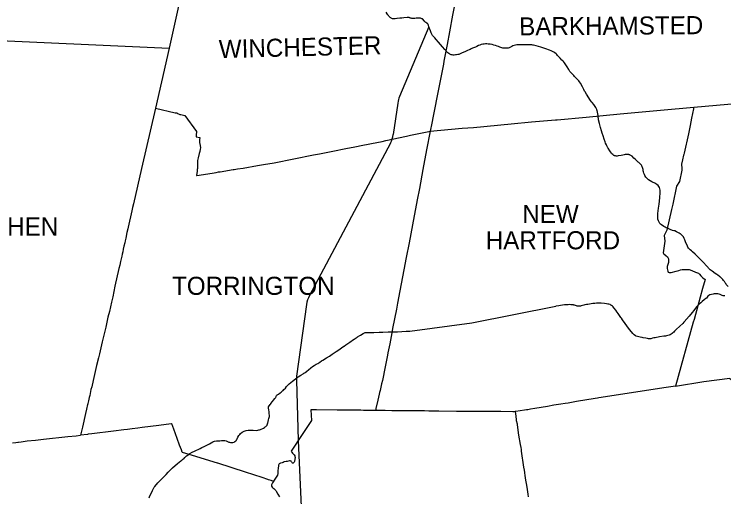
# Model space of a CAD drawing. Extents: x 0 to 2603, y -226 to 830.
# Drawn here: x 107.7 to 160.6, y 640.7 to 676.8 of the extents above; entities that cross this region are included whole.
import ezdxf

# ---------------------------------------------------------------- set-up
doc = ezdxf.new("R2010")
doc.units = 0
for name, color, linetype in [('CT_TSH_Map_Town_Limits', 7, 'Continuous'), ('CT_TSH_Map_Town_Text', 7, 'Continuous'), ('CT_TSH_Map_US_and_State_Routes', 7, 'Continuous')]:
    doc.layers.add(name, color=color, linetype=linetype)

msp = doc.modelspace()

# ---------------------------------------------------------------- linework, layer by layer
at = {"layer": 'CT_TSH_Map_Town_Limits'}
for points in [[(142.198, 686.552), (142.15, 686.309), (141.745, 684.019), (141.62, 683.255), (141.187, 680.773), (141.113, 680.321), (140.913, 679.551), (140.896, 679.495), (140.856, 679.291), (140.811, 679.034), (140.725, 678.584), (140.613, 677.959), (140.441, 677.067), (140.378, 676.703), (140.137, 675.45), (139.965, 674.513), (139.87, 673.997), (139.728, 673.254), (139.696, 673.043), (139.23, 670.666), (139.03, 669.643), (138.929, 669.148), (138.837, 668.643), (138.715, 668.03)], [(121.633, 685.104), (119.215, 674.224)], [(158.379, 669.838), (162.606, 670.208), (162.883, 670.24), (164.49, 676.032)], [(102.09, 675.051), (103.633, 674.96), (104.397, 674.915), (119.215, 674.224)], [(119.215, 674.224), (118.649, 671.731), (118.2, 669.749)], [(118.2, 669.749), (117.164, 665.263), (116.552, 662.607), (116.484, 662.337), (116.435, 662.092), (116.155, 660.872), (116.132, 660.754), (116.067, 660.483), (115.974, 660.058), (115.924, 659.853), (115.898, 659.704), (115.842, 659.46), (115.792, 659.222), (115.75, 659.042), (115.711, 658.853), (115.675, 658.719), (115.656, 658.612), (115.581, 658.301), (115.529, 658.04), (115.469, 657.797), (115.172, 656.465), (115.002, 655.668), (114.915, 655.285), (114.757, 654.582), (114.652, 654.145), (114.486, 653.4), (114.225, 652.315), (114.008, 651.411), (113.945, 651.123), (113.803, 650.538), (113.545, 649.439), (113.44, 648.961), (113.383, 648.747), (113.288, 648.307), (113.244, 648.148), (113.191, 647.91), (113.142, 647.716), (113.137, 647.673), (113.128, 647.645), (113.055, 647.299), (112.975, 646.965), (112.748, 645.947), (112.6, 645.343)], [(118.2, 669.749), (119.677, 669.399), (119.779, 669.406), (119.811, 669.396), (119.852, 669.362), (119.914, 669.326), (120.027, 669.29), (120.093, 669.275), (120.385, 669.209), (121.257, 668.008), (121.24, 667.739), (121.239, 667.613), (121.512, 667.574), (121.499, 667.534), (121.485, 667.407), (121.479, 667.265), (121.489, 667.18), (121.537, 666.977), (121.553, 666.796), (121.538, 666.691), (121.5, 666.52), (121.458, 666.372), (121.381, 666.039), (121.333, 665.856), (121.327, 665.818), (121.325, 665.545), (121.326, 665.239), (121.322, 665.183), (121.303, 665.048), (121.276, 664.882), (121.251, 664.751), (121.251, 664.718), (121.296, 664.719), (122.432, 664.911), (122.724, 664.957), (122.914, 664.998), (123.018, 665.011), (123.991, 665.165), (124.062, 665.181), (124.326, 665.223), (124.732, 665.272), (125.821, 665.465), (126.26, 665.545), (127.055, 665.68), (129.985, 666.26), (130.438, 666.343), (131.303, 666.52), (132.523, 666.761), (132.683, 666.791), (133.077, 666.873), (133.327, 666.917), (133.425, 666.938), (134.32, 667.119), (135.112, 667.266), (135.389, 667.336), (136.942, 667.672), (137.236, 667.739), (138.346, 667.956), (138.594, 668.002), (138.715, 668.03)], [(138.715, 668.03), (141.105, 668.267), (141.946, 668.323), (144.741, 668.577), (146.266, 668.722), (148.059, 668.879), (148.182, 668.885), (150.341, 669.081), (152.882, 669.326), (155.889, 669.604), (158.379, 669.838)], [(158.379, 669.838), (158.356, 669.731), (158.35, 669.716), (158.225, 668.997), (158.115, 668.455), (157.987, 667.849), (157.658, 666.398), (157.631, 666.293), (157.625, 666.242), (157.551, 665.895), (157.46, 665.575), (157.501, 665.245), (157.501, 665.202), (157.49, 665.117), (157.322, 664.293), (157.102, 663.932), (156.822, 662.594), (156.729, 662.193), (156.374, 660.637), (156.177, 660.244), (156.229, 659.818), (156.086, 658.969), (156.115, 658.909), (156.157, 658.871), (156.294, 658.77), (156.413, 658.662), (156.503, 658.508), (156.499, 658.338), (156.488, 658.225), (156.448, 658.087), (156.414, 658.002), (156.397, 657.938), (156.405, 657.789), (156.434, 657.577), (156.478, 657.522), (156.546, 657.5), (156.606, 657.489), (156.691, 657.481), (157.073, 657.591), (157.271, 657.632), (157.382, 657.683), (157.511, 657.718), (157.621, 657.702), (157.71, 657.701), (157.95, 657.711), (158.028, 657.704), (158.234, 657.638), (158.349, 657.58), (158.414, 657.569), (158.521, 657.515), (158.729, 657.429), (158.801, 657.367), (158.918, 657.242), (159.015, 657.13), (159.07, 657.082), (159.233, 656.974), (159.044, 656.284), (158.868, 655.66), (158.406, 653.991), (158.341, 653.771), (157.01, 649.012)], [(138.715, 668.03), (138.442, 666.636), (138.157, 665.173), (137.897, 663.749), (137.734, 662.921), (137.379, 661.04), (137.125, 659.715), (136.915, 658.619), (136.743, 657.691), (136.443, 656.131), (136.274, 655.205), (136.179, 654.759), (135.897, 653.303), (135.842, 652.982), (135.686, 652.172), (135.546, 651.492), (135.514, 651.323), (135.337, 650.456), (135.145, 649.434), (135.07, 649.187), (134.984, 648.808), (134.96, 648.687), (134.922, 648.544), (134.892, 648.4), (134.789, 647.968), (134.645, 647.327), (134.639, 647.294), (134.617, 647.192)], [(157.01, 649.012), (159.123, 649.343), (161.084, 649.599), (161.103, 649.564), (161.183, 649.498), (161.265, 649.448), (161.464, 649.358), (161.647, 649.3), (161.679, 649.27), (161.707, 649.232), (161.785, 649.202), (161.84, 649.175), (161.903, 649.128), (161.948, 649.066), (161.955, 649.043), (162.08, 649.071)], [(157.01, 649.012), (156.316, 648.905), (151.307, 648.125), (151.199, 648.11), (151.032, 648.081), (149.636, 647.86), (149.013, 647.749), (148.789, 647.715), (148.45, 647.671), (148.122, 647.607), (147.927, 647.576), (147.454, 647.493), (146.521, 647.337), (146.192, 647.286), (146.003, 647.252), (145.899, 647.238), (145.747, 647.208), (145.093, 647.104), (145.056, 647.103)], [(134.617, 647.192), (134.487, 647.186), (134.418, 647.19), (133.922, 647.196), (133.865, 647.197), (133.731, 647.199), (133.538, 647.206), (132.768, 647.208), (131.76, 647.217), (130.22, 647.239), (129.79, 647.247), (129.788, 647.242), (129.844, 646.433), (129.349, 645.698), (128.996, 645.168), (128.466, 644.37), (128.32, 644.148), (128.352, 644.11), (128.383, 644.088), (128.433, 644.01), (128.485, 643.968), (128.546, 643.886), (128.59, 643.798), (128.612, 643.748), (128.622, 643.683), (128.604, 643.549), (128.572, 643.39), (128.539, 643.323), (128.506, 643.277), (128.475, 643.263), (128.439, 643.267), (128.397, 643.293), (128.371, 643.324), (128.344, 643.36), (128.317, 643.402), (128.293, 643.415), (128.263, 643.422), (128.193, 643.422), (128.026, 643.393), (127.963, 643.388), (127.794, 643.349), (127.723, 643.321), (127.655, 643.289), (127.542, 643.257), (127.489, 643.234), (127.441, 643.203), (127.415, 643.166), (127.392, 643.109), (127.346, 642.825), (127.335, 642.729), (127.335, 642.488), (127.313, 642.371), (127.269, 642.283), (127.017, 641.921), (127.001, 641.895)], [(145.056, 647.103), (145.029, 647.091), (144.875, 647.095), (143.983, 647.109), (143.9, 647.118), (143.772, 647.115), (143.404, 647.112), (142.695, 647.12), (142.233, 647.119), (141.861, 647.114), (141.771, 647.122), (141.467, 647.127), (140.67, 647.127), (139.362, 647.14), (138.849, 647.15), (138.614, 647.149), (138.275, 647.156), (137.236, 647.166), (135.849, 647.176), (135.355, 647.184), (134.663, 647.189), (134.617, 647.192)], [(145.056, 647.103), (145.067, 646.963), (145.119, 646.527), (145.131, 646.449), (145.188, 646.202), (145.209, 646.109), (145.302, 645.357), (145.425, 644.657), (145.466, 644.433), (145.485, 644.281), (145.508, 644.148), (145.671, 642.958), (145.713, 642.726), (145.743, 642.568), (145.753, 642.536), (145.771, 642.34), (145.806, 642.159), (145.806, 642.132), (145.908, 641.466), (145.943, 641.292), (146.002, 640.945), (146.03, 640.736)], [(127.001, 641.895), (126.834, 641.954), (126.641, 642.015), (126.595, 642.035), (126.157, 642.184), (124.919, 642.584), (122.852, 643.259), (122.831, 643.263), (120.953, 643.843), (120.216, 644.064), (120.19, 644.081), (120.129, 644.248), (119.997, 644.605), (119.823, 645.095), (119.571, 645.786), (119.426, 646.203), (119.404, 646.196), (118.987, 646.141), (118.448, 646.081), (117.828, 645.998), (117.203, 645.921), (116.879, 645.88), (116.469, 645.834), (116.103, 645.784), (115.827, 645.753), (115.072, 645.651), (113.449, 645.453), (113.164, 645.419), (113.128, 645.41), (112.6, 645.343)], [(107.53, 644.765), (107.764, 644.793), (107.914, 644.817), (107.978, 644.832), (108.159, 644.854), (108.627, 644.928), (109.235, 644.981), (109.832, 645.051), (111.645, 645.242), (112.265, 645.303), (112.6, 645.343)], [(127.001, 641.895), (126.923, 641.781), (126.875, 641.698), (126.855, 641.631), (126.868, 641.535), (126.899, 641.476), (126.962, 641.421), (127.024, 641.375), (127.125, 641.278), (127.173, 641.225), (127.212, 641.171), (127.331, 640.938), (127.455, 640.745)]]:
    msp.add_lwpolyline(points, dxfattribs=at)
at = {"layer": 'CT_TSH_Map_US_and_State_Routes'}
for p, q in [((136.978, 676.521), (136.726, 676.497)), ((138.02, 676.454), (137.987, 676.462)), ((138.613, 675.826), (136.422, 670.631)), ((138.613, 675.826), (138.57, 675.933)), ((138.726, 675.535), (138.613, 675.826)), ((138.789, 675.371), (138.726, 675.535)), ((138.996, 675.059), (138.884, 675.188)), ((145.747, 674.481), (145.443, 674.489)), ((140.087, 673.833), (140.025, 673.88)), ((147.186, 674.227), (146.962, 674.299)), ((147.333, 674.178), (147.186, 674.227)), ((148.4, 673.482), (148.204, 673.695)), ((148.535, 673.348), (148.4, 673.482)), ((148.729, 673.131), (148.66, 673.228)), ((149.794, 671.794), (149.481, 672.125)), ((150.384, 670.79), (150.264, 670.974)), ((136.285, 670.139), (135.946, 667.791)), ((135.733, 667.138), (129.69, 655.768)), ((152.115, 666.563), (151.992, 666.761)), ((155.24, 664.255), (154.995, 664.416)), ((156.141, 660.934), (155.965, 661.05)), ((157.999, 659.308), (157.95, 659.388)), ((158.536, 658.799), (158.477, 658.857)), ((158.75, 658.592), (158.536, 658.799)), ((160.173, 657.28), (160.097, 657.335)), ((129.475, 655.103), (128.737, 649.759)), ((133.25, 652.66), (133.281, 652.681)), ((133.281, 652.681), (133.456, 652.789)), ((133.456, 652.789), (133.505, 652.818)), ((133.95, 653.009), (134.044, 653.009)), ((134.361, 653.018), (134.494, 653.021)), ((135.965, 653.061), (136.264, 653.073)), ((132.415, 652.096), (132.706, 652.298)), ((132.706, 652.298), (132.973, 652.484)), ((131.817, 651.679), (132.253, 651.983)), ((130.698, 650.944), (130.968, 651.111)), ((130.968, 651.111), (131.187, 651.252)), ((131.187, 651.252), (131.395, 651.391)), ((129.926, 650.467), (130.056, 650.548)), ((130.056, 650.548), (130.201, 650.638)), ((130.201, 650.638), (130.317, 650.71)), ((130.317, 650.71), (130.464, 650.8)), ((130.464, 650.8), (130.602, 650.885)), ((130.602, 650.885), (130.698, 650.944)), ((129.491, 650.126), (129.63, 650.237)), ((129.63, 650.237), (129.804, 650.38)), ((129.804, 650.38), (129.926, 650.467)), ((128.714, 649.593), (128.747, 649.62)), ((128.747, 649.62), (128.79, 649.651)), ((128.79, 649.651), (128.827, 649.68)), ((128.827, 649.68), (128.859, 649.701)), ((128.859, 649.701), (129.049, 649.823)), ((129.049, 649.823), (129.225, 649.931)), ((129.225, 649.931), (129.279, 649.966)), ((128.719, 649.425), (128.853, 644.968)), ((127.581, 648.568), (127.682, 648.653)), ((127.682, 648.653), (127.723, 648.691)), ((127.723, 648.691), (127.791, 648.756)), ((127.791, 648.756), (127.892, 648.865)), ((126.926, 647.852), (127.019, 647.968)), ((127.019, 647.968), (127.111, 648.084)), ((127.205, 648.226), (127.216, 648.271)), ((127.216, 648.271), (127.233, 648.297)), ((127.233, 648.297), (127.24, 648.307)), ((126.623, 647.471), (126.748, 647.628)), ((126.639, 647.37), (126.623, 647.471)), ((126.748, 647.628), (126.801, 647.692)), ((126.577, 646.249), (126.638, 646.481)), ((125.956, 645.751), (126.041, 645.778)), ((122.078, 644.636), (122.221, 644.709)), ((122.951, 644.933), (122.992, 644.937)), ((128.854, 644.938), (129.353, 633.855)), ((121.523, 644.361), (121.646, 644.421)), ((121.646, 644.421), (121.838, 644.514)), ((121.838, 644.514), (122.078, 644.636)), ((118.385, 641.782), (118.599, 642.008)), ((117.717, 640.676), (117.788, 640.822))]:
    msp.add_line(p, q, dxfattribs=at)
for points in [[(135.977, 676.419), (135.934, 676.42), (135.89, 676.427), (135.845, 676.439), (135.797, 676.46), (135.755, 676.487), (135.717, 676.517), (135.658, 676.57), (135.615, 676.617), (135.582, 676.667), (135.555, 676.714), (135.492, 676.804), (135.42, 676.906)], [(136.726, 676.497), (136.584, 676.481), (136.433, 676.465), (136.241, 676.446)], [(137.103, 676.526), (137.078, 676.532), (137.025, 676.531), (136.978, 676.521)], [(137.196, 676.49), (137.168, 676.507), (137.137, 676.52), (137.103, 676.526)], [(137.295, 676.46), (137.244, 676.472), (137.196, 676.49)], [(136.241, 676.446), (136.206, 676.443), (136.082, 676.429), (135.977, 676.419)], [(137.461, 676.442), (137.395, 676.444), (137.344, 676.451), (137.295, 676.46)], [(137.65, 676.467), (137.566, 676.45), (137.512, 676.445), (137.461, 676.442)], [(137.987, 676.462), (137.941, 676.47), (137.892, 676.477), (137.816, 676.481), (137.751, 676.479), (137.693, 676.474), (137.65, 676.467)], [(138.123, 676.422), (138.093, 676.433), (138.02, 676.454)], [(138.463, 676.103), (138.414, 676.136), (138.382, 676.154), (138.346, 676.181), (138.318, 676.206), (138.272, 676.254), (138.123, 676.422)], [(138.524, 676.037), (138.508, 676.06), (138.496, 676.073), (138.479, 676.089), (138.463, 676.103)], [(138.57, 675.933), (138.544, 676.001), (138.524, 676.037)], [(138.884, 675.188), (138.834, 675.268), (138.8, 675.336), (138.789, 675.371)], [(139.32, 674.685), (139.153, 674.878), (139.055, 674.993), (138.996, 675.059)], [(140.025, 673.88), (139.945, 673.958), (139.894, 674.02), (139.865, 674.059), (139.811, 674.124), (139.634, 674.326), (139.472, 674.511), (139.32, 674.685)], [(142.32, 674.423), (142.18, 674.361), (142.076, 674.316), (141.867, 674.22)], [(143.904, 674.312), (143.815, 674.357), (143.711, 674.393), (143.587, 674.434), (143.469, 674.466), (143.321, 674.495), (143.177, 674.522), (143.033, 674.541), (142.937, 674.545), (142.842, 674.543), (142.735, 674.535), (142.625, 674.518), (142.518, 674.493), (142.415, 674.461), (142.32, 674.423)], [(145.443, 674.489), (145.337, 674.49), (145.251, 674.487), (145.166, 674.478), (145.074, 674.462), (144.977, 674.434), (144.883, 674.398), (144.808, 674.36)], [(146.51, 674.441), (146.416, 674.458), (146.372, 674.463), (146.281, 674.468), (145.747, 674.481)], [(146.962, 674.299), (146.621, 674.41), (146.51, 674.441)], [(141.055, 673.854), (140.933, 673.8), (140.845, 673.77), (140.773, 673.751), (140.679, 673.732), (140.603, 673.723), (140.507, 673.718), (140.42, 673.721), (140.346, 673.727), (140.278, 673.739), (140.215, 673.763)], [(141.867, 674.22), (141.767, 674.174), (141.701, 674.144), (141.611, 674.106), (141.485, 674.047), (141.33, 673.978), (141.055, 673.854)], [(144.531, 674.243), (144.45, 674.227), (144.389, 674.222), (144.317, 674.22), (144.231, 674.221), (144.128, 674.237), (144.051, 674.257), (143.972, 674.284), (143.904, 674.312)], [(144.808, 674.36), (144.711, 674.304), (144.657, 674.28), (144.595, 674.26), (144.531, 674.243)], [(148.204, 673.695), (148.152, 673.753), (148.101, 673.801), (148.017, 673.873), (147.93, 673.935), (147.842, 673.989), (147.729, 674.045), (147.614, 674.087), (147.333, 674.178)], [(140.215, 673.763), (140.172, 673.784), (140.138, 673.803), (140.087, 673.833)], [(148.66, 673.228), (148.605, 673.279), (148.535, 673.348)], [(149.481, 672.125), (149.425, 672.189), (149.26, 672.369), (149.138, 672.495), (149.073, 672.597), (149.048, 672.641), (148.932, 672.828), (148.729, 673.131)], [(150.069, 671.336), (149.919, 671.618), (149.859, 671.71), (149.794, 671.794)], [(150.264, 670.974), (150.232, 671.02), (150.163, 671.15), (150.069, 671.336)], [(151.14, 669.665), (151.096, 669.749), (151.061, 669.811), (151.02, 669.876), (150.965, 669.949), (150.91, 670.02), (150.789, 670.168), (150.753, 670.22), (150.679, 670.338), (150.384, 670.79)], [(151.253, 669.06), (151.248, 669.218), (151.223, 669.327), (151.193, 669.457), (151.167, 669.58), (151.156, 669.615), (151.14, 669.665)], [(151.992, 666.761), (151.978, 666.793), (151.902, 666.943), (151.867, 667.007), (151.803, 667.138), (151.769, 667.23), (151.694, 667.44), (151.617, 667.682), (151.548, 667.897), (151.503, 668.058), (151.43, 668.321), (151.35, 668.612), (151.276, 668.875), (151.264, 668.972), (151.253, 669.06)], [(152.391, 666.237), (152.359, 666.258), (152.329, 666.285), (152.273, 666.343), (152.231, 666.393), (152.165, 666.488), (152.115, 666.563)], [(152.527, 666.184), (152.496, 666.192), (152.465, 666.204), (152.447, 666.212), (152.42, 666.222), (152.391, 666.237)], [(153.559, 666.279), (153.528, 666.288), (153.498, 666.293), (153.464, 666.299), (153.412, 666.304), (153.356, 666.303), (153.305, 666.3), (153.249, 666.291), (153.193, 666.28), (153.081, 666.258), (152.955, 666.232), (152.739, 666.185), (152.676, 666.177), (152.583, 666.177), (152.527, 666.184)], [(154.233, 665.733), (154.015, 665.937), (153.92, 666.031), (153.784, 666.164), (153.741, 666.196), (153.693, 666.225), (153.645, 666.248), (153.598, 666.267), (153.559, 666.279)], [(154.469, 665.49), (154.425, 665.548), (154.385, 665.594), (154.341, 665.638), (154.295, 665.677), (154.28, 665.691), (154.233, 665.733)], [(154.63, 664.994), (154.617, 665.076), (154.605, 665.173), (154.583, 665.262), (154.563, 665.318), (154.533, 665.382), (154.498, 665.445), (154.469, 665.49)], [(154.995, 664.416), (154.881, 664.517), (154.805, 664.608), (154.736, 664.724), (154.698, 664.798), (154.653, 664.907), (154.63, 664.994)], [(155.716, 663.98), (155.627, 664.063), (155.551, 664.112), (155.464, 664.15), (155.301, 664.226), (155.24, 664.255)], [(155.708, 661.887), (155.746, 662.301), (155.794, 662.596), (155.85, 663.054), (155.886, 663.451), (155.88, 663.625), (155.859, 663.732), (155.824, 663.828), (155.772, 663.915), (155.716, 663.98)], [(155.965, 661.05), (155.911, 661.097), (155.859, 661.154), (155.789, 661.255), (155.743, 661.35), (155.712, 661.459), (155.694, 661.58), (155.698, 661.713), (155.708, 661.887)], [(156.624, 660.695), (156.517, 660.737), (156.448, 660.77), (156.392, 660.799), (156.319, 660.832), (156.256, 660.868), (156.141, 660.934)], [(156.904, 660.602), (156.799, 660.63), (156.624, 660.695)], [(157.776, 659.785), (157.712, 659.939), (157.675, 660.032), (157.605, 660.152), (157.551, 660.219), (157.503, 660.27), (157.452, 660.316), (157.419, 660.345), (157.376, 660.376), (157.29, 660.43), (157.085, 660.527), (156.959, 660.587), (156.904, 660.602)], [(157.95, 659.388), (157.912, 659.457), (157.776, 659.785)], [(158.477, 658.857), (158.29, 659.035), (158.212, 659.105), (158.104, 659.188), (158.071, 659.222), (157.999, 659.308)], [(159.379, 657.944), (159.06, 658.283), (158.75, 658.592)], [(160.097, 657.335), (159.98, 657.417), (159.752, 657.581), (159.608, 657.697), (159.487, 657.819), (159.458, 657.856), (159.379, 657.944)], [(160.947, 656.433), (160.871, 656.516), (160.812, 656.586), (160.768, 656.656), (160.718, 656.73), (160.666, 656.82), (160.612, 656.894), (160.554, 656.958), (160.52, 656.994), (160.501, 657.011), (160.479, 657.032), (160.448, 657.065), (160.391, 657.125), (160.358, 657.156), (160.336, 657.171), (160.311, 657.185), (160.268, 657.212), (160.173, 657.28)], [(160.692, 655.747), (160.586, 655.76), (160.512, 655.777), (160.448, 655.799), (160.355, 655.839), (160.29, 655.863), (160.188, 655.889), (160.084, 655.899), (160.012, 655.899), (159.91, 655.891), (159.819, 655.875), (159.695, 655.851), (159.585, 655.811), (159.511, 655.771), (159.441, 655.719), (159.376, 655.647), (159.324, 655.579), (159.278, 655.537), (159.168, 655.441), (159.015, 655.318)], [(159.015, 655.318), (158.912, 655.229), (158.797, 655.122), (158.621, 654.942), (158.522, 654.833), (158.376, 654.653), (158.252, 654.494), (158.043, 654.234), (157.677, 653.807), (157.642, 653.773), (157.556, 653.695)], [(136.264, 653.073), (136.911, 653.102), (137.115, 653.111), (137.183, 653.114), (141.815, 653.742), (148.08, 654.973)], [(148.31, 655.012), (148.113, 654.979), (148.08, 654.973)], [(148.421, 655.029), (148.31, 655.012)], [(148.593, 655.052), (148.421, 655.029)], [(149.42, 655.061), (149.407, 655.066), (149.362, 655.074), (149.307, 655.081), (149.217, 655.088), (149.097, 655.089), (149.011, 655.087), (148.919, 655.084), (148.811, 655.076), (148.721, 655.067), (148.593, 655.052)], [(149.487, 655.044), (149.42, 655.061)], [(150.249, 655.068), (150.182, 655.054), (150.072, 655.027), (149.974, 654.996), (149.933, 654.986), (149.88, 654.977), (149.828, 654.971), (149.771, 654.971), (149.71, 654.976), (149.673, 654.984), (149.628, 654.995), (149.553, 655.021), (149.487, 655.044)], [(152.601, 654.627), (152.581, 654.653), (152.421, 654.858), (152.36, 654.927), (152.311, 654.974), (152.253, 655.018), (152.201, 655.051), (152.131, 655.089), (152.053, 655.118), (152.014, 655.129), (151.96, 655.131), (151.858, 655.142), (151.717, 655.166), (151.477, 655.188), (151.262, 655.195), (151.127, 655.192), (151, 655.185), (150.854, 655.17), (150.723, 655.152), (150.592, 655.127), (150.471, 655.102), (150.377, 655.09), (150.249, 655.068)], [(152.945, 654.126), (152.833, 654.287), (152.73, 654.435), (152.601, 654.627)], [(152.978, 654.076), (152.945, 654.126)], [(153.265, 653.682), (153.067, 653.953), (152.978, 654.076)], [(154.273, 652.678), (154.175, 652.701), (154.092, 652.734), (154.026, 652.766), (153.935, 652.832), (153.879, 652.882), (153.83, 652.935), (153.735, 653.051), (153.588, 653.24), (153.396, 653.502), (153.265, 653.682)], [(157.077, 653.236), (157.025, 653.182), (156.949, 653.099), (156.884, 653.031), (156.819, 652.975), (156.76, 652.93), (156.688, 652.891)], [(157.344, 653.494), (157.077, 653.236)], [(157.556, 653.695), (157.344, 653.494)], [(132.973, 652.484), (133.032, 652.525), (133.25, 652.66)], [(133.505, 652.818), (133.702, 652.942), (133.757, 652.97), (133.809, 652.99), (133.849, 653)], [(133.849, 653), (133.88, 653.005), (133.913, 653.01), (133.95, 653.009)], [(134.044, 653.009), (134.215, 653.014), (134.361, 653.018)], [(134.494, 653.021), (134.898, 653.034), (135.181, 653.041), (135.577, 653.052), (135.937, 653.061), (135.965, 653.061)], [(154.519, 652.636), (154.381, 652.662), (154.273, 652.678)], [(156.688, 652.891), (156.621, 652.847), (156.538, 652.81), (156.442, 652.781), (156.356, 652.761), (156.266, 652.75), (156.143, 652.737), (155.822, 652.681), (155.509, 652.62)], [(154.617, 652.614), (154.519, 652.636)], [(155.166, 652.547), (155.093, 652.543), (155.001, 652.545), (154.935, 652.554), (154.794, 652.582), (154.617, 652.614)], [(155.509, 652.62), (155.4, 652.603), (155.313, 652.579), (155.166, 652.547)], [(131.395, 651.391), (131.683, 651.584), (131.817, 651.679)], [(132.253, 651.983), (132.273, 651.997), (132.415, 652.096)], [(129.279, 649.966), (129.346, 650.009), (129.372, 650.027), (129.382, 650.035), (129.461, 650.099), (129.491, 650.126)], [(128.526, 649.449), (128.553, 649.471), (128.647, 649.546), (128.664, 649.557)], [(128.664, 649.557), (128.683, 649.568), (128.714, 649.593)], [(127.892, 648.865), (127.988, 648.978), (128.039, 649.037), (128.113, 649.117), (128.183, 649.176)], [(128.183, 649.176), (128.436, 649.374), (128.526, 649.449)], [(127.303, 648.37), (127.339, 648.394), (127.376, 648.418)], [(127.376, 648.418), (127.494, 648.503), (127.581, 648.568)], [(127.111, 648.084), (127.147, 648.127), (127.182, 648.173), (127.197, 648.201), (127.205, 648.226)], [(127.24, 648.307), (127.259, 648.331), (127.283, 648.354), (127.303, 648.37)], [(126.688, 646.998), (126.676, 647.086), (126.653, 647.241), (126.639, 647.37)], [(126.801, 647.692), (126.817, 647.712), (126.926, 647.852)], [(126.703, 646.731), (126.71, 646.774), (126.708, 646.848), (126.695, 646.942), (126.688, 646.998)], [(126.638, 646.481), (126.664, 646.582), (126.703, 646.731)], [(126.041, 645.778), (126.25, 645.879), (126.338, 645.926), (126.397, 645.966), (126.431, 645.989), (126.48, 646.04)], [(126.48, 646.04), (126.506, 646.071), (126.527, 646.107), (126.529, 646.112), (126.545, 646.143)], [(126.545, 646.143), (126.558, 646.175), (126.569, 646.209), (126.577, 646.249)], [(124.292, 645.083), (124.349, 645.21), (124.425, 645.325), (124.484, 645.397), (124.549, 645.463), (124.677, 645.567), (124.82, 645.642), (124.975, 645.696), (125.129, 645.724), (125.252, 645.721), (125.5, 645.718), (125.708, 645.709), (125.831, 645.721), (125.924, 645.737), (125.956, 645.751)], [(122.221, 644.709), (122.477, 644.846), (122.535, 644.874)], [(122.535, 644.874), (122.611, 644.899), (122.743, 644.916), (122.896, 644.931), (122.951, 644.933)], [(122.992, 644.937), (123.127, 644.948), (123.234, 644.95), (123.37, 644.942)], [(123.37, 644.942), (123.472, 644.924), (123.53, 644.904)], [(123.53, 644.904), (123.676, 644.838), (123.712, 644.824)], [(123.712, 644.824), (123.791, 644.801), (123.875, 644.792), (123.969, 644.796), (124.071, 644.817), (124.129, 644.865), (124.184, 644.921), (124.238, 644.984), (124.277, 645.043), (124.292, 645.083)], [(120.521, 643.799), (120.649, 643.891), (120.772, 643.972), (120.942, 644.072), (121.113, 644.163), (121.523, 644.361)], [(120.082, 643.429), (120.16, 643.484), (120.247, 643.547), (120.302, 643.59), (120.394, 643.671), (120.521, 643.799)], [(119.143, 642.588), (119.316, 642.764), (119.462, 642.906), (119.831, 643.235), (120.082, 643.429)], [(118.599, 642.008), (118.805, 642.226), (118.899, 642.325), (118.988, 642.42), (119.143, 642.588)], [(117.788, 640.822), (117.889, 641.033), (117.974, 641.22), (118.063, 641.409), (118.102, 641.471), (118.146, 641.527), (118.385, 641.782)]]:
    msp.add_lwpolyline(points, dxfattribs=at)
for centre, start, end in [((138.265, 669.853), 157.1321, 171.7866), ((133.967, 668.077), 332.012, 351.7866), ((131.456, 654.829), 152.012, 172.1346), ((130.718, 649.485), 172.1346, 181.7242), ((130.852, 645.028), 181.7242, 182.5784)]:
    msp.add_arc(centre, 2, start, end, dxfattribs=at)

# ---------------------------------------------------------------- texts
at = {"layer": 'CT_TSH_Map_Town_Text'}
for s, rotation, p in [('BARKHAMSTED', 0.4289, (145.353, 675.178)), ('WINCHESTER', 1.423, (122.945, 673.483)), ('TORRINGTON', 360, (119.434, 655.821))]:
    msp.add_text(s, height=1.35, rotation=rotation, dxfattribs=at).set_placement(p)
for s, p in [('NEW', (145.582, 661.187)), ('GOSHEN', (103.116, 660.248)), ('HARTFORD', (142.852, 659.221))]:
    msp.add_text(s, height=1.35, dxfattribs=at).set_placement(p)

doc.saveas('drawing.dxf')
